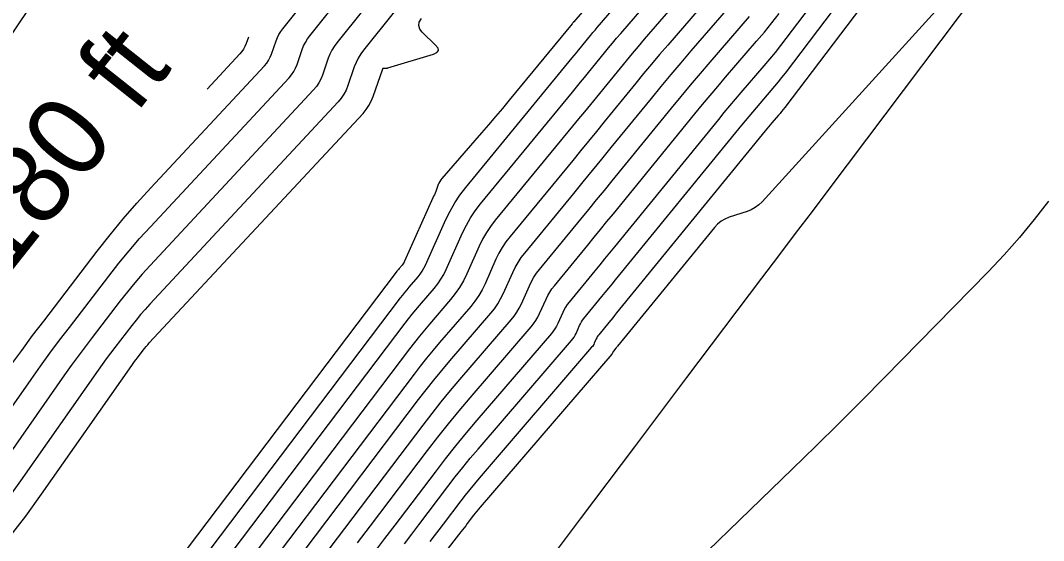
# Model space of a CAD drawing. Extents: x 7585033 to 7595090, y 547091 to 553471.
# Drawn here: x 7587567.9 to 7587648.2, y 548269.9 to 548310.7 of the extents above; entities that cross this region are included whole.
import ezdxf

# ---------------------------------------------------------------- set-up
doc = ezdxf.new("R2010")
doc.units = 0
for name, color, linetype in [('E_TERR_DSPLAY_GeneralTx', 7, 'Continuous'), ('E_TERR_DSPLAY_MajContour', 7, 'Continuous'), ('E_TERR_DSPLAY_MinContour', 7, 'Continuous')]:
    doc.layers.add(name, color=color, linetype=linetype)

msp = doc.modelspace()

# ---------------------------------------------------------------- linework, layer by layer
at = {"layer": 'E_TERR_DSPLAY_MajContour'}
for points in [[(7587566.409, 548344.76), (7587568.885, 548346.082), (7587571.567, 548346.907), (7587574.457, 548347.233), (7587586.431, 548347.542), (7587588.846, 548347.296), (7587590.105, 548346.403), (7587590.206, 548344.864), (7587589.15, 548342.678), (7587572.744, 548317.488), (7587572.41, 548316.983), (7587572.068, 548316.484), (7587571.718, 548315.991), (7587571.361, 548315.502), (7587569.916, 548313.56), (7587569.557, 548313.072), (7587569.204, 548312.581), (7587568.857, 548312.085), (7587568.516, 548311.585), (7587564.024, 548304.928)], [(7587624.889, 548326.325), (7587611.348, 548310.623), (7587611.337, 548310.61), (7587611.326, 548310.597), (7587611.315, 548310.584), (7587611.305, 548310.571), (7587611.251, 548310.505), (7587611.218, 548310.465), (7587606.289, 548304.467), (7587605.754, 548303.82), (7587605.214, 548303.176), (7587604.669, 548302.537), (7587604.12, 548301.901), (7587600.997, 548298.31), (7587600.91, 548298.201), (7587600.834, 548298.085), (7587600.767, 548297.963), (7587600.712, 548297.835), (7587600.51, 548297.31), (7587600.459, 548297.179), (7587600.405, 548297.048), (7587600.351, 548296.919), (7587600.294, 548296.79), (7587598.072, 548291.829), (7587598.032, 548291.747), (7587597.986, 548291.669), (7587597.935, 548291.594), (7587597.878, 548291.523), (7587597.638, 548291.245), (7587597.579, 548291.175), (7587597.521, 548291.104), (7587597.464, 548291.033), (7587597.408, 548290.96), (7587577.104, 548264.133)], [(7587639.237, 548324.093), (7587628.013, 548309.297), (7587627.592, 548308.751), (7587627.163, 548308.212), (7587626.725, 548307.68), (7587626.279, 548307.154), (7587624.478, 548305.066), (7587624.03, 548304.542), (7587623.585, 548304.016), (7587623.144, 548303.486), (7587622.706, 548302.954), (7587614.545, 548292.953), (7587614.16, 548292.481), (7587613.775, 548292.01), (7587613.389, 548291.54), (7587613.003, 548291.069), (7587610.988, 548288.617), (7587610.843, 548288.428), (7587610.711, 548288.231), (7587610.593, 548288.026), (7587610.489, 548287.812), (7587610.098, 548286.94), (7587609.993, 548286.726), (7587609.874, 548286.522), (7587609.74, 548286.327), (7587609.591, 548286.142), (7587603.75, 548279.353), (7587602.903, 548278.353), (7587602.072, 548277.341), (7587601.258, 548276.315), (7587600.459, 548275.276), (7587597.295, 548271.097), (7587596.503, 548270.053), (7587595.707, 548269.012)], [(7587567.16, 548283.66), (7587568.006, 548284.826), (7587568.865, 548285.983), (7587569.737, 548287.13), (7587573.939, 548292.604), (7587574.946, 548293.885), (7587575.984, 548295.14), (7587577.051, 548296.371), (7587578.147, 548297.577), (7587587.069, 548307.155), (7587587.244, 548307.365), (7587587.396, 548307.589), (7587587.522, 548307.828), (7587587.625, 548308.081), (7587587.985, 548309.124), (7587588.085, 548309.379), (7587588.206, 548309.623), (7587588.348, 548309.856), (7587588.51, 548310.077), (7587598.126, 548322.089)], [(7587624.312, 548315.265), (7587618.729, 548308.79), (7587618.093, 548308.048), (7587617.462, 548307.301), (7587616.836, 548306.55), (7587616.216, 548305.795), (7587613.744, 548302.765), (7587613.125, 548302.008), (7587612.506, 548301.252), (7587611.887, 548300.496), (7587611.266, 548299.74), (7587606.347, 548293.753), (7587606.027, 548293.336), (7587605.736, 548292.9), (7587605.476, 548292.446), (7587605.245, 548291.974), (7587604.382, 548290.046), (7587604.15, 548289.575), (7587603.886, 548289.124), (7587603.59, 548288.693), (7587603.261, 548288.283), (7587600.822, 548285.448), (7587600.306, 548284.838), (7587599.799, 548284.22), (7587599.302, 548283.595), (7587598.815, 548282.962), (7587587.564, 548268.097)], [(7587567.032, 548270.141), (7587568.319, 548271.822), (7587569.559, 548273.539), (7587576.648, 548283.642), (7587576.756, 548283.794), (7587576.866, 548283.945), (7587576.977, 548284.095), (7587577.09, 548284.244), (7587577.546, 548284.838), (7587577.661, 548284.985), (7587577.78, 548285.129), (7587577.903, 548285.27), (7587578.028, 548285.408), (7587594.805, 548303.421), (7587595.057, 548303.721), (7587595.274, 548304.042), (7587595.455, 548304.383), (7587595.602, 548304.746), (7587596.35, 548306.914), (7587596.365, 548306.945), (7587596.387, 548306.967), (7587596.416, 548306.98), (7587596.451, 548306.983), (7587596.604, 548306.976), (7587596.642, 548306.976), (7587596.68, 548306.979), (7587596.717, 548306.985), (7587596.754, 548306.994), (7587600.336, 548308.076), (7587600.608, 548308.199), (7587600.727, 548308.359), (7587600.693, 548308.555), (7587600.507, 548308.788), (7587599.46, 548309.794), (7587599.259, 548310.05), (7587599.18, 548310.313), (7587599.224, 548310.585), (7587599.39, 548310.864)]]:
    msp.add_lwpolyline(points, dxfattribs=at)
at = {"layer": 'E_TERR_DSPLAY_MinContour'}
for points in [[(7587610.001, 548269.104), (7587610.945, 548270.362), (7587611.89, 548271.619), (7587616.139, 548277.268), (7587617.162, 548278.628), (7587618.187, 548279.987), (7587619.212, 548281.346), (7587620.238, 548282.704), (7587626.124, 548290.487), (7587627.446, 548292.237), (7587628.768, 548293.988), (7587630.09, 548295.739), (7587631.41, 548297.491), (7587646.042, 548316.914), (7587646.127, 548317.027), (7587646.212, 548317.139), (7587646.297, 548317.251), (7587646.382, 548317.364), (7587646.724, 548317.812), (7587646.81, 548317.924), (7587646.896, 548318.036), (7587646.982, 548318.147), (7587647.069, 548318.259), (7587659.826, 548334.634)], [(7587611.769, 548329.529), (7587594.854, 548308.399), (7587594.628, 548308.09), (7587594.43, 548307.766), (7587594.262, 548307.427), (7587594.122, 548307.071), (7587593.62, 548305.617), (7587593.477, 548305.263), (7587593.301, 548304.931), (7587593.09, 548304.618), (7587592.845, 548304.327), (7587578.058, 548288.45), (7587577.69, 548288.045), (7587577.331, 548287.632), (7587576.983, 548287.21), (7587576.644, 548286.779), (7587575.309, 548285.041), (7587574.978, 548284.605), (7587574.652, 548284.165), (7587574.33, 548283.722), (7587574.013, 548283.275), (7587567.923, 548274.595), (7587566.782, 548273.016)], [(7587607.053, 548326.839), (7587592.739, 548308.958), (7587592.534, 548308.679), (7587592.356, 548308.385), (7587592.203, 548308.078), (7587592.076, 548307.755), (7587591.622, 548306.438), (7587591.492, 548306.118), (7587591.332, 548305.817), (7587591.141, 548305.534), (7587590.919, 548305.27), (7587578.088, 548291.492), (7587577.477, 548290.82), (7587576.882, 548290.134), (7587576.304, 548289.435), (7587575.742, 548288.721), (7587573.529, 548285.838), (7587572.979, 548285.114), (7587572.438, 548284.384), (7587571.904, 548283.649), (7587571.378, 548282.908), (7587566.287, 548275.652)], [(7587564.651, 548276.709), (7587568.743, 548282.541), (7587569.478, 548283.577), (7587570.224, 548284.604), (7587570.98, 548285.623), (7587571.748, 548286.634), (7587574.84, 548290.662), (7587575.625, 548291.66), (7587576.433, 548292.637), (7587577.264, 548293.596), (7587578.117, 548294.534), (7587588.994, 548306.212), (7587589.193, 548306.449), (7587589.364, 548306.703), (7587589.507, 548306.973), (7587589.623, 548307.26), (7587590.03, 548308.44), (7587590.144, 548308.729), (7587590.281, 548309.004), (7587590.441, 548309.267), (7587590.624, 548309.517), (7587602.337, 548324.149)], [(7587598.053, 548269.643), (7587598.625, 548270.391), (7587599.194, 548271.142), (7587601.469, 548274.146), (7587602.043, 548274.893), (7587602.629, 548275.63), (7587603.226, 548276.358), (7587603.835, 548277.077), (7587611.174, 548285.606), (7587611.277, 548285.736), (7587611.371, 548285.872), (7587611.454, 548286.014), (7587611.527, 548286.163), (7587611.8, 548286.771), (7587611.873, 548286.921), (7587611.955, 548287.064), (7587612.047, 548287.201), (7587612.148, 548287.333), (7587613.553, 548289.044), (7587613.823, 548289.372), (7587614.092, 548289.7), (7587614.361, 548290.029), (7587614.629, 548290.357), (7587624.548, 548302.512), (7587624.83, 548302.855), (7587625.114, 548303.196), (7587625.4, 548303.535), (7587625.689, 548303.872), (7587626.849, 548305.217), (7587627.136, 548305.555), (7587627.418, 548305.898), (7587627.694, 548306.245), (7587627.965, 548306.597), (7587641.165, 548323.997)], [(7587643.092, 548323.9), (7587627.918, 548303.897), (7587627.797, 548303.74), (7587627.673, 548303.585), (7587627.547, 548303.431), (7587627.419, 548303.28), (7587626.9, 548302.679), (7587626.771, 548302.528), (7587626.643, 548302.376), (7587626.516, 548302.224), (7587626.39, 548302.071), (7587614.713, 548287.762), (7587614.561, 548287.576), (7587614.409, 548287.39), (7587614.257, 548287.204), (7587614.104, 548287.018), (7587613.308, 548286.049), (7587613.251, 548285.974), (7587613.199, 548285.897), (7587613.152, 548285.815), (7587613.111, 548285.731), (7587612.957, 548285.386), (7587612.915, 548285.302), (7587612.868, 548285.221), (7587612.815, 548285.144), (7587612.756, 548285.071), (7587603.919, 548274.801), (7587603.549, 548274.363), (7587603.185, 548273.92), (7587602.828, 548273.471), (7587602.478, 548273.016), (7587601.094, 548271.187), (7587600.747, 548270.73), (7587600.398, 548270.274), (7587600.048, 548269.819)], [(7587579.719, 548265.124), (7587597.76, 548288.96), (7587597.924, 548289.173), (7587598.091, 548289.383), (7587598.261, 548289.591), (7587598.434, 548289.796), (7587599.135, 548290.61), (7587599.302, 548290.819), (7587599.453, 548291.038), (7587599.587, 548291.268), (7587599.705, 548291.507), (7587601.312, 548295.095), (7587601.637, 548295.762), (7587602.005, 548296.402), (7587602.414, 548297.017), (7587602.866, 548297.605), (7587611.23, 548307.784), (7587611.393, 548307.983), (7587611.556, 548308.182), (7587611.719, 548308.381), (7587611.882, 548308.58), (7587612.532, 548309.377), (7587612.696, 548309.575), (7587612.86, 548309.773), (7587613.026, 548309.969), (7587613.193, 548310.165), (7587624.745, 548323.56)], [(7587582.334, 548266.115), (7587598.112, 548286.961), (7587598.383, 548287.314), (7587598.66, 548287.662), (7587598.943, 548288.007), (7587599.23, 548288.346), (7587600.393, 548289.697), (7587600.67, 548290.043), (7587600.919, 548290.407), (7587601.142, 548290.788), (7587601.338, 548291.186), (7587602.623, 548294.055), (7587602.917, 548294.657), (7587603.249, 548295.235), (7587603.618, 548295.79), (7587604.026, 548296.321), (7587611.242, 548305.103), (7587611.558, 548305.487), (7587611.873, 548305.872), (7587612.188, 548306.256), (7587612.503, 548306.642), (7587613.76, 548308.183), (7587614.076, 548308.567), (7587614.394, 548308.949), (7587614.715, 548309.329), (7587615.039, 548309.706), (7587624.601, 548320.795)], [(7587624.457, 548318.03), (7587616.884, 548309.248), (7587616.404, 548308.688), (7587615.928, 548308.125), (7587615.456, 548307.558), (7587614.988, 548306.989), (7587613.123, 548304.703), (7587612.657, 548304.132), (7587612.19, 548303.562), (7587611.722, 548302.991), (7587611.254, 548302.421), (7587605.187, 548295.037), (7587604.823, 548294.563), (7587604.492, 548294.068), (7587604.196, 548293.551), (7587603.934, 548293.014), (7587602.953, 548290.823), (7587602.689, 548290.287), (7587602.389, 548289.774), (7587602.052, 548289.284), (7587601.679, 548288.818), (7587600.026, 548286.897), (7587599.624, 548286.422), (7587599.23, 548285.941), (7587598.843, 548285.454), (7587598.463, 548284.961), (7587584.949, 548267.106)], [(7587590.179, 548269.088), (7587599.167, 548280.962), (7587599.762, 548281.736), (7587600.369, 548282.5), (7587600.987, 548283.254), (7587601.618, 548283.999), (7587604.844, 548287.747), (7587605.127, 548288.101), (7587605.383, 548288.473), (7587605.611, 548288.863), (7587605.811, 548289.27), (7587606.556, 548290.933), (7587606.755, 548291.341), (7587606.98, 548291.733), (7587607.231, 548292.109), (7587607.507, 548292.469), (7587611.351, 548297.147), (7587612.087, 548298.044), (7587612.823, 548298.942), (7587613.558, 548299.84), (7587614.293, 548300.739), (7587617.444, 548304.601), (7587618.217, 548305.542), (7587618.996, 548306.477), (7587619.782, 548307.407), (7587620.574, 548308.332), (7587624.57, 548312.965)], [(7587640.527, 548312.323), (7587626.145, 548296.499), (7587625.885, 548296.247), (7587625.6, 548296.035), (7587625.289, 548295.862), (7587624.953, 548295.728), (7587623.557, 548295.273), (7587623.222, 548295.137), (7587622.917, 548294.96), (7587622.641, 548294.739), (7587622.395, 548294.476), (7587614.797, 548285.166), (7587614.762, 548285.123), (7587614.726, 548285.079), (7587614.69, 548285.036), (7587614.655, 548284.992), (7587614.468, 548284.765), (7587614.455, 548284.748), (7587614.442, 548284.729), (7587614.432, 548284.71), (7587614.422, 548284.69), (7587614.386, 548284.61), (7587614.376, 548284.59), (7587614.365, 548284.571), (7587614.353, 548284.553), (7587614.339, 548284.536), (7587604.004, 548272.525), (7587603.871, 548272.368), (7587603.741, 548272.21), (7587603.613, 548272.049), (7587603.488, 548271.886), (7587602.993, 548271.232), (7587602.869, 548271.068), (7587602.744, 548270.905), (7587602.619, 548270.742), (7587602.493, 548270.58), (7587590.15, 548254.696)], [(7587591.908, 548268.912), (7587592.794, 548270.079), (7587599.518, 548278.962), (7587600.221, 548279.876), (7587600.938, 548280.779), (7587601.669, 548281.67), (7587602.414, 548282.549), (7587606.426, 548287.212), (7587606.665, 548287.51), (7587606.88, 548287.823), (7587607.072, 548288.151), (7587607.24, 548288.493), (7587607.867, 548289.893), (7587608.034, 548290.236), (7587608.224, 548290.566), (7587608.435, 548290.882), (7587608.667, 548291.185), (7587611.901, 548295.121), (7587612.521, 548295.876), (7587613.14, 548296.631), (7587613.759, 548297.387), (7587614.377, 548298.144), (7587619.023, 548303.837), (7587619.772, 548304.749), (7587620.527, 548305.655), (7587621.289, 548306.557), (7587622.056, 548307.453), (7587625.14, 548311.028)], [(7587594.381, 548269.715), (7587595.396, 548271.052), (7587599.87, 548276.963), (7587600.681, 548278.017), (7587601.508, 548279.058), (7587602.351, 548280.085), (7587603.21, 548281.1), (7587608.009, 548286.677), (7587608.202, 548286.919), (7587608.377, 548287.173), (7587608.532, 548287.438), (7587608.669, 548287.716), (7587609.178, 548288.852), (7587609.314, 548289.131), (7587609.467, 548289.398), (7587609.639, 548289.655), (7587609.827, 548289.901), (7587612.452, 548293.095), (7587612.955, 548293.708), (7587613.457, 548294.321), (7587613.959, 548294.934), (7587614.461, 548295.548), (7587620.864, 548303.395), (7587621.458, 548304.118), (7587622.056, 548304.836), (7587622.659, 548305.55), (7587623.267, 548306.26), (7587625.709, 548309.091), (7587626.314, 548309.804), (7587626.907, 548310.525), (7587627.49, 548311.256)], [(7587585.801, 548309.41), (7587585.626, 548308.902), (7587585.537, 548308.682), (7587585.427, 548308.475), (7587585.296, 548308.28), (7587585.143, 548308.098), (7587582.571, 548305.337)], [(7587648.622, 548296.535), (7587647.505, 548295.091), (7587646.341, 548293.687), (7587645.131, 548292.322), (7587643.875, 548290.997), (7587635.744, 548282.704), (7587633.957, 548280.893), (7587632.158, 548279.093), (7587630.347, 548277.305), (7587628.525, 548275.529), (7587617.711, 548265.06)]]:
    msp.add_lwpolyline(points, dxfattribs=at)

# ---------------------------------------------------------------- texts
at = {"layer": 'E_TERR_DSPLAY_GeneralTx'}
msp.add_text('180 ft', height=6.3, rotation=51.58273, dxfattribs=at).set_placement((7587566.757, 548290.465))

doc.saveas('drawing.dxf')
